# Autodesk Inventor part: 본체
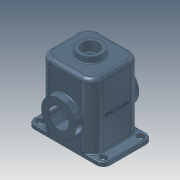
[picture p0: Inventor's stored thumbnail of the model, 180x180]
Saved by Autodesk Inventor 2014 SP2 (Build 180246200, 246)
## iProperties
Company: 한국ATC센터
Created: 2014-10
Part Number: 본체
Document SubType Name: Modeling
Designer: 한국ATC센터
Density: 2.71 g/cm^3
Material: 알루미늄 6061
Mass: 1088.52 g
Surface Area: 2150.09 cm^2
Volume: 1088.52 cm^3
Appearance: 청회색(진함/광택)
Author: KYOUNG IL JANG
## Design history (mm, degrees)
sketch "스케치1"
  geometry: L1 (-70, 65)-(70, 65); L2 (70, 65)-(70, -65); L3 (70, -65)-(-70, -65); L4 (-70, -65)-(-70, 65); 3 further points
  constraints: 8 end point, 2 midpoint, 2 parallel, 1 horizontal, 1 horizontal alignment, 1 perpendicular, 1 vertical alignment
  dimensions: "d0" = 140 distance of L2.end L3.end; "d68" = 130 distance of L3.end L1.start
extrude "돌출1" new body sketch "스케치1" distance "d1" = 180; taper "d2" = 0 deg
fillet "모깎기1" dims "d3" = 20
feature "쉘1" dims "d4" = 10
sketch "스케치2"
  geometry: L1 (-70, 45)-(-70, -45) reference; L2 (-50, -65)-(-82, -65); L3 (-82, 65)-(-50, 65); L4 (-85, 57)-(-82, 57); L5 (-82, 41)-(-85, 41); L6 (-100, 47)-(-100, -47); A1 r 20 centre (-50, 45) between (-50, 65) and (-70, 45) reference; A2 r 20 centre (-50, -45) between (-70, -45) and (-50, -65) reference; A3 r 8 centre (-82, 49) between (-82, 41) and (-82, 57); A4 r 8 centre (-85, 49) between (-85, 57) and (-85, 41); A5 r 18 centre (-82, 47) between (-82, 65) and (-100, 47); A6 r 18 centre (-82, -47) between (-100, -47) and (-82, -65); 1 further point
  constraints: 10 end point, 9 tangent, 8 point on circle, 4 centre point, 2 parallel, 2 perpendicular, 1 equal radius
  dimensions: "d6" = 49 vertical distance of point (0, 0) A3.centre; "d8" = 16 distance between parallel lines of L4 L5; "d64" = 18 radius of A5; "d65" = 12 distance from line of A3.centre L1; "d66" = 30 distance between parallel lines of L6 L1; "d67" = 3 distance of A4.centre A3.centre
extrude "돌출2" join sketch "스케치2" distance "d9" = 10; taper "d10" = 0 deg
extrude "돌출3" cut sketch "스케치2" stored distance "d11" = 10; taper "d12" = 0 deg
sketch "스케치3"
  geometry: L1 (-65, 0)-(-65, 180) reference; L2 (-55, 0)-(-55, 170) reference; L3 (-83, 75)-(-51, 75); L4 (45, 0)-(-45, 0) reference; L5 (-83, 75)-(-83, 120.5); L6 (-83, 120.5)-(-55, 120.5); L7 (-55, 120.5)-(-51, 116.5); L8 (-51, 116.5)-(-51, 75); 2 further points
  constraints: 10 end point, 4 perpendicular, 1 point on line
  dimensions: "d13" = 75 distance between parallel lines of L3 L4; "d14" = 18 distance from line of L1 L3.start; "d15" = 4 distance from line of L3.end L2; "d16" = 91 diameter of L6 L3; "d17" = 135 deg angle of L7 L2
revolve "회전1" sketch "스케치3" stored, may be unused: angle "d18" = 90 deg
sketch "스케치4"
  geometry: C1 r 45.5 at (0, 0) reference; 2 further points
  constraints: 1 vertical alignment
  dimensions: "d19" = 35 distance of C1.centre point (0, 35)
hole "구멍1" sketch "스케치4" at (0, 35) diameter "d20" = 3.459; stored, may be unused: countersink angle "d24" = 90 deg, drill point angle "d26" = 118 deg; dims "d21" = 13, "d22" = 4, "d23" = 2, "d25" = 16
fillet "모깎기2" dims "d30" = 3
hole "구멍2" diameter "d33" = 52; stored, may be unused: countersink angle "d37" = 90 deg, drill point angle "d39" = 118 deg; dims "d31" = 10, "d32" = 10, "d34" = 13, "d35" = 4, "d36" = 2, "d38" = 16
sketch "스케치5"
  geometry: C1 r 31 at (0, 0); 1 further point
  constraints: 1 centre point, 1 coincident
  dimensions: "d40" = 62 diameter of C1
extrude "돌출4" join sketch "스케치5" distance "d41" = 15; taper "d42" = 0 deg
hole "구멍3" diameter "d45" = 43; stored, may be unused: countersink angle "d49" = 90 deg, drill point angle "d51" = 118 deg; dims "d43" = 10, "d44" = 10, "d46" = 13, "d47" = 4, "d48" = 2, "d50" = 16
fillet "모깎기3" dims "d52" = 3
fillet "모깎기4" dims "d53" = 3
chamfer "모따기1" distance "d55" = 1; stored, may be unused: second distance "d56" = 2, angle "d57" = 45 deg
sketch "스케치6"
  geometry: 2 further points
  constraints: 1 vertical alignment, 1 other
  dimensions: "d71" = 90 distance of point (0, 0) point (0, 90)
feature "엠보싱2" sketch "스케치6" dims "d0" = 140, "d68" = 130, "d72" = 1, "d73" = 0
fillet "모깎기6" dims "d74" = 10
sketch "스케치7"
  geometry: C1 r 15 at (0, 0); C2 r 21.5 at (0, 0) reference; C3 r 25 at (0, 0); 1 further point
  constraints: 2 centre point, 2 coincident
  dimensions: "d61" = 30 diameter of C1; "d75" = 50 diameter of C3
extrude "돌출5" join sketch "스케치7" distance "d62" = 10; taper "d63" = 0 deg
feature "면 이동1" dims "d76" = 1
fillet "모깎기7" dims "d77" = 3
node "솔리드1"
mirror "대칭1"
mirror "대칭2"
pattern_circular "원형 패턴1" dims angle "d28" = 360 deg
mirror "대칭3"
